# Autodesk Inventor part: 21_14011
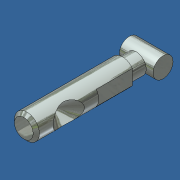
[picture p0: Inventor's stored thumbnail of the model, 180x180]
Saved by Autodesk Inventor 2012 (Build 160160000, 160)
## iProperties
Created: 2006-12
Part Number: 21_14011
Material: Steel
Document SubType Name: Modeling
Designer: Andy Moles
Density: 7.85 g/cm^3
Mass: 30.1607 g
Surface Area: 19.9364 cm^2
Volume: 3.84212 cm^3
Author: Andy Moles
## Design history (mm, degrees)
sketch "Sketch1"
  geometry: C1 r 4 at (0, 0); 1 further point
  constraints: 1 centre point, 1 coincident
  dimensions: "d0" = 8 diameter of C1
extrude "Extrusion1" new body sketch "Sketch1" stored distance "d1" = 13.5; taper "d2" = 0 deg
workplane "Work Plane2"
sketch "Sketch2"
  geometry: C1 r 5 at (0, 0); 1 further point
  constraints: 1 centre point, 1 coincident
  dimensions: "d5" = 10 diameter of C1
extrude "Extrusion2" join sketch "Sketch2" distance "d6" = 45; taper "d7" = 0 deg
chamfer "Chamfer1" distance "d8" = 1.25; stored, may be unused: second distance "d9" = 2, angle "d10" = 45 deg
sketch "Sketch3"
  geometry: L1 (5, 0)-(-5, 0) reference; L2 (-4, 3)-(-4, -3); L3 (4, 3)-(4, -3); A1 r 5 centre (0, 0) between (5, 0) and (-5, 0) reference; A2 r 5 centre (0, 0) between (-5, 0) and (5, 0) reference; 4 further points
  constraints: 4 end point, 4 midpoint, 4 point on circle, 2 horizontal alignment, 2 parallel, 1 vertical
  dimensions: "d11" = 8 distance between parallel lines of L3 L2
extrude "Extrusion3" cut sketch "Sketch3" distance "d12" = 20; taper "d13" = 0 deg
workplane "Work Plane3"
sketch "Sketch4"
  geometry: L1 (0, 0)-(0, 6) reference; L2 (20, 6)-(20, 3) reference; 4 further points
  constraints: 2 horizontal alignment, 1 midpoint
  dimensions: "d15" = 32 distance from line of point (-12, 3) L2
hole "Hole1" sketch "Sketch4" at (-12, 3) diameter "d16" = 0.1; stored, may be unused: countersink angle "d20" = 90 deg, drill point angle "d22" = 118 deg; dims "d17" = 6, "d18" = 12.5, "d19" = 2, "d21" = 6.25
sketch "Sketch5"
  geometry: L1 (-4, 3)-(-4, 0) reference; L2 (4, 0)-(-4, 0) reference; L3 (4, 0)-(4, 3) reference; L4 (4, 3)-(4, -3); L5 (-4, 3)-(-4, -3); C1 r 4 at (0, 0); A1 r 5 centre (0, 0) between (4, 3) and (-4, 3) reference; A2 r 5 centre (0, 0) between (4, -3) and (-4, -3)
  constraints: 4 end point, 2 centre point, 2 coincident, 2 point on circle, 1 collinear, 1 concentric, 1 point on line, 1 tangent
extrude "Extrusion4" cut sketch "Sketch5" distance "d24" = 5.5; taper "d25" = 0 deg
mirror "Mirror1"
body "Solid1"
other parameters: "d4" = 4, "d14" = 1
